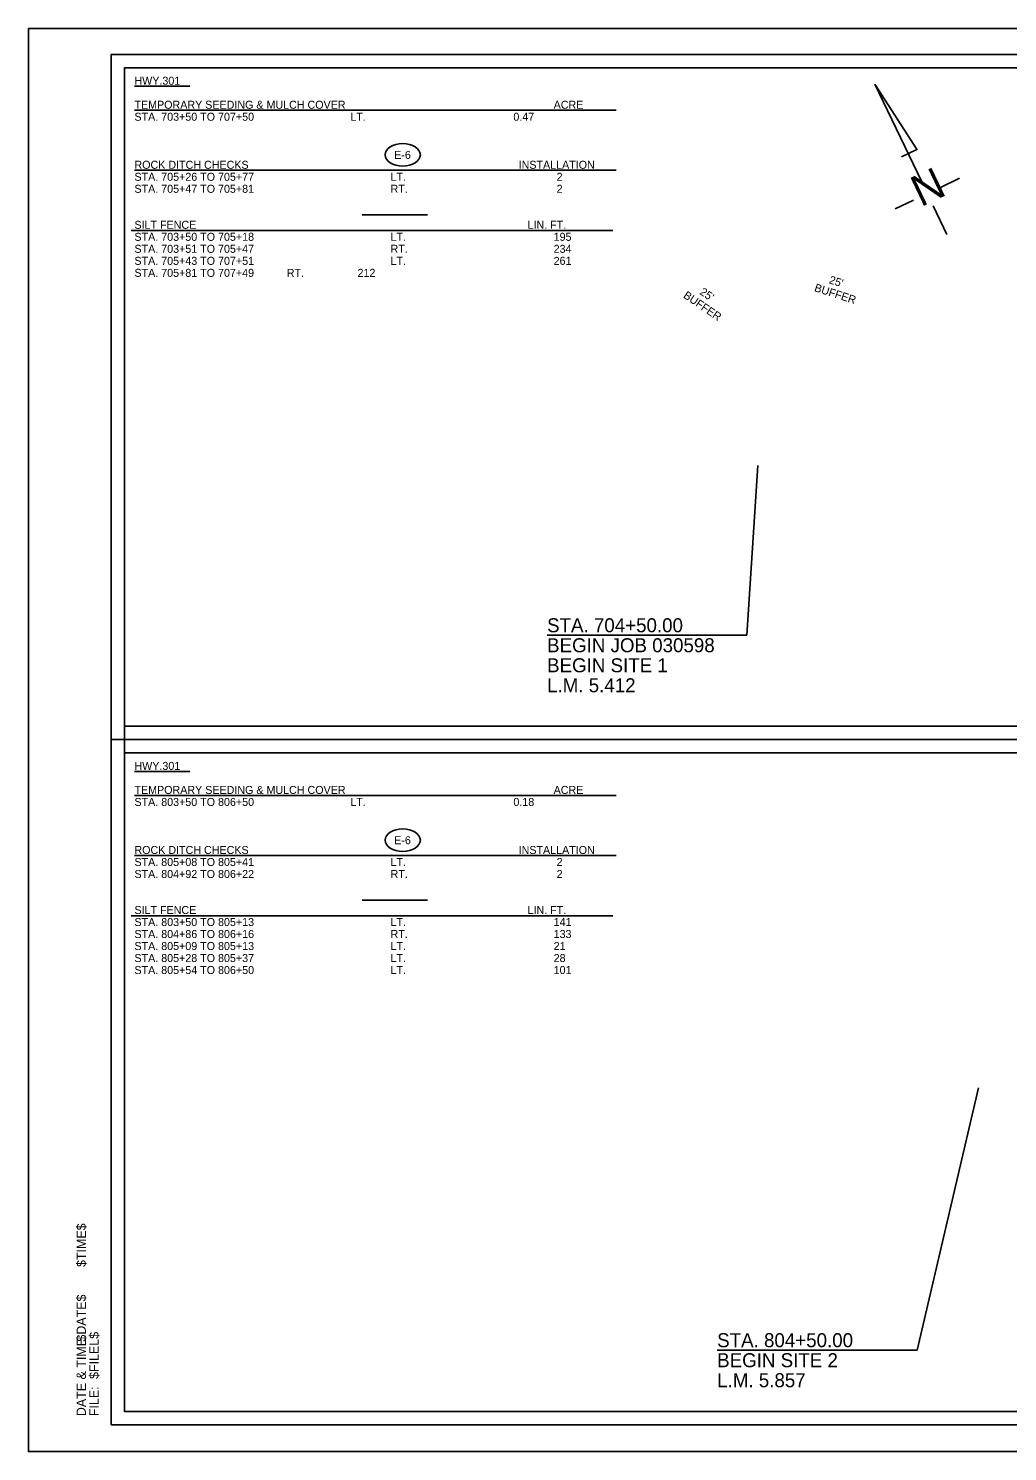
# Model space of a CAD drawing. Extents: x 814841 to 962585, y -174183 to 1802800.
# Drawn here: x 814841 to 815574, y 1801733 to 1802800 of the extents above; entities that cross this region are included whole.
import ezdxf

# ---------------------------------------------------------------- set-up
doc = ezdxf.new("R2010")
doc.units = 0
for name, color, linetype in [('Default', 7, 'Continuous'), ('Erosion Legend', 7, 'Continuous'), ('R_Border', 7, 'Continuous'), ('R_Border Notes', 7, 'Continuous'), ('R_Border Plan-Plan', 7, 'Continuous'), ('R_Detour Annot', 7, 'Continuous'), ('R_Draft', 7, 'Continuous'), ('R_No Plot', 7, 'Continuous'), ('Veg Buffer_Annot', 7, 'Continuous')]:
    doc.layers.add(name, color=color, linetype=linetype)

# ---------------------------------------------------------------- blocks, each defined once
blk = doc.blocks.new('E-6')
at = {"layer": 'Default'}
blk.add_ellipse((0, 0), major_axis=(13.2, 0), ratio=0.638788, dxfattribs=at)
blk.add_text('E-6', height=6, dxfattribs=at).set_placement((-6.4, -3))

msp = doc.modelspace()

# ---------------------------------------------------------------- linework, layer by layer
at = {"layer": 'Erosion Legend'}
for p, q in [((814920, 1802756.8), (814961.6, 1802756.8)), ((814920, 1802738.8), (815281, 1802738.8)), ((814920, 1802693.8), (815281, 1802693.8)), ((815090.7, 1802660.5), (815139.6, 1802660.5)), ((814917.6, 1802648.6), (815278.6, 1802648.6)), ((814920, 1802243.2), (814961.6, 1802243.2)), ((814920, 1802225.2), (815281, 1802225.2)), ((814920, 1802180.2), (815281, 1802180.2)), ((815090.7, 1802146.8), (815139.6, 1802146.8)), ((814917.6, 1802135), (815278.6, 1802135))]:
    msp.add_line(p, q, dxfattribs=at)
at = {"layer": 'R_Border'}
for p, q in [((814902.6, 1802780.6), (816483.5, 1802780.6)), ((814902.6, 1801753.3), (814902.6, 1802780.6)), ((814902.6, 1801753.3), (814902.6, 1801753.3)), ((816483.5, 1801753.3), (814902.6, 1801753.3))]:
    msp.add_line(p, q, dxfattribs=at)
at = {"layer": 'R_Border Plan-Plan'}
msp.add_line((814902.6, 1802267), (816483.5, 1802267), dxfattribs=at)
at = {"layer": 'R_Draft'}
for p, q in [((815475.1, 1802758.4), (815506.8, 1802709)), ((815510.2, 1802685), (815475.1, 1802758.4)), ((815494.9, 1802703.8), (815506.6, 1802709.4)), ((815523.6, 1802680.7), (815538.5, 1802687.8)), ((815490.2, 1802664.8), (815504.1, 1802671.4)), ((815529, 1802645.6), (815518.7, 1802667.2)), ((815379, 1802345.3), (815387.2, 1802472.5)), ((815379, 1802345.3), (815229.3, 1802345.3)), ((815506.8, 1801809.3), (815552.7, 1802006.1)), ((815506.8, 1801809.3), (815356.8, 1801809.3))]:
    msp.add_line(p, q, dxfattribs=at)
at = {"layer": 'R_No Plot'}
for points in [[(814840.5, 1802800.1), (816507.2, 1802800.1), (816507.2, 1801733.4), (814840.5, 1801733.4)], [(816473.5, 1802277), (814912.6, 1802277), (814912.6, 1802770.6), (816160.3, 1802770.6), (816160.3, 1802721.2), (816248, 1802721.2), (816368.5, 1802721.2), (816368.5, 1802609.5), (816473.5, 1802609.5)], [(814912.6, 1802770.6), (816160.3, 1802770.6), (816160.3, 1802721.2), (816248, 1802721.2), (816368.5, 1802721.2), (816368.5, 1802609.5), (816473.5, 1802609.5), (816473.5, 1801763.3), (814912.6, 1801763.3)], [(816473.5, 1802277), (814912.6, 1802277), (814912.6, 1802770.6), (816160.3, 1802770.6), (816160.3, 1802721.2), (816248, 1802721.2), (816368.5, 1802721.2), (816368.5, 1802609.5), (816473.5, 1802609.5)], [(814912.6, 1802257), (816473.5, 1802257), (816473.5, 1801763.3), (814912.6, 1801763.3)], [(814912.6, 1802257), (816473.5, 1802257), (816473.5, 1801763.3), (814912.6, 1801763.3)]]:
    msp.add_lwpolyline(points, close=True, dxfattribs=at)

# ---------------------------------------------------------------- block references
at = {"layer": 'Erosion Legend', "rotation": -1.8065126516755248e-10}
for p in [(815121.1, 1802705.3), (815121.1, 1802191.6)]:
    msp.add_blockref('E-6', p, dxfattribs=at)

# ---------------------------------------------------------------- texts
at = {"layer": 'Erosion Legend'}
for s, p in [('HWY.301', (814920, 1802757.9)), ('TEMPORARY SEEDING & MULCH COVER', (814920, 1802739.9)), (' ACRE', (815232, 1802739.9)), ('STA. 703+50 TO 707+50', (814920, 1802730.9)), ('        LT.    ', (815064, 1802730.9)), ('         0.47', (815184, 1802730.9)), ('ROCK DITCH CHECKS', (814920, 1802694.9)), ('INSTALLATION', (815208, 1802694.9)), ('STA. 705+26 TO 705+77', (814920, 1802685.9)), ('STA. 705+47 TO 705+81', (814920, 1802676.9)), ('LT.', (815112, 1802685.9)), ('RT.', (815112, 1802676.9)), ('  2', (815232, 1802685.9)), ('  2', (815232, 1802676.9)), ('SILT FENCE', (814920, 1802649.9)), ('   LIN. FT.', (815208, 1802649.9)), ('STA. 703+50 TO 705+18', (814920, 1802640.9)), ('LT.', (815112, 1802640.9)), (' 195', (815232, 1802640.9)), ('STA. 703+51 TO 705+47 ', (814920, 1802631.9)), ('STA. 705+43 TO 707+51', (814920, 1802622.9)), ('RT. ', (815112, 1802631.9)), ('LT.', (815112, 1802622.9)), (' 234', (815232, 1802631.9)), (' 261', (815232, 1802622.9)), ('STA. 705+81 TO 707+49           RT.                  212', (814920, 1802613.9)), ('HWY.301', (814920, 1802244.3)), ('TEMPORARY SEEDING & MULCH COVER', (814920, 1802226.3)), ('STA. 803+50 TO 806+50', (814920, 1802217.3)), ('        LT.    ', (815064, 1802217.3)), ('         0.18', (815184, 1802217.3)), (' ACRE', (815232, 1802226.3)), ('ROCK DITCH CHECKS', (814920, 1802181.3)), ('INSTALLATION', (815208, 1802181.3)), ('STA. 805+08 TO 805+41', (814920, 1802172.3)), ('LT.', (815112, 1802172.3)), ('  2', (815232, 1802172.3)), ('STA. 804+92 TO 806+22', (814920, 1802163.3)), ('RT.', (815112, 1802163.3)), ('  2', (815232, 1802163.3)), ('SILT FENCE', (814920, 1802136.3)), ('   LIN. FT.', (815208, 1802136.3)), ('STA. 803+50 TO 805+13', (814920, 1802127.3)), ('LT.', (815112, 1802127.3)), (' 141', (815232, 1802127.3)), ('STA. 804+86 TO 806+16 ', (814920, 1802118.3)), ('RT. ', (815112, 1802118.3)), (' 133', (815232, 1802118.3)), ('STA. 805+09 TO 805+13', (814920, 1802109.3)), ('STA. 805+28 TO 805+37', (814920, 1802100.3)), ('LT.', (815112, 1802109.3)), ('LT. ', (815112, 1802100.3)), (' 21', (815232, 1802109.3)), (' 28', (815232, 1802100.3)), ('STA. 805+54 TO 806+50', (814920, 1802091.3)), ('LT.  ', (815112, 1802091.3)), (' 101', (815232, 1802091.3))]:
    msp.add_text(s, height=6, dxfattribs=at).set_placement(p)
at = {"layer": 'R_Border Notes'}
for s, height, p in [('$TIME$', 6.98, (814883.6, 1801871.7)), ('$DATE$', 6.98, (814883.6, 1801815.8)), ('DATE & TIME:', 6.984, (814883.6, 1801759.9)), ('$FILEL$', 6.98, (814893.2, 1801787.8)), ('FILE: ', 6.98, (814893.2, 1801759.9))]:
    msp.add_text(s, height=height, rotation=90, dxfattribs=at).set_placement(p)
at = {"layer": 'R_Detour Annot'}
for s, p in [('STA. 704+50.00', (815229.3, 1802347.5)), ('BEGIN JOB 030598 ', (815229.3, 1802332.5)), ('BEGIN SITE 1', (815229.3, 1802317.5)), ('L.M. 5.412', (815229.3, 1802302.5)), ('STA. 804+50.00 ', (815356.8, 1801811.6)), ('BEGIN SITE 2', (815356.8, 1801796.6)), ('L.M. 5.857', (815356.8, 1801781.6))]:
    msp.add_text(s, height=10.5, dxfattribs=at).set_placement(p)
at = {"layer": 'R_Draft'}
msp.add_text('N', height=23.3, rotation=25.5319, dxfattribs=at).set_placement((815509.5, 1802666))
at = {"layer": 'Veg Buffer_Annot'}
for s, rotation, p in [('BUFFER', 342.1183, (815429.2, 1802603.3)), ("25'", 342.1183, (815440.2, 1802609.2)), ('BUFFER', 325.6564, (815330.9, 1802598.7)), ("25'", 325.6564, (815343.2, 1802601.3))]:
    msp.add_text(s, height=6, rotation=rotation, dxfattribs=at).set_placement(p)

doc.saveas('drawing.dxf')
